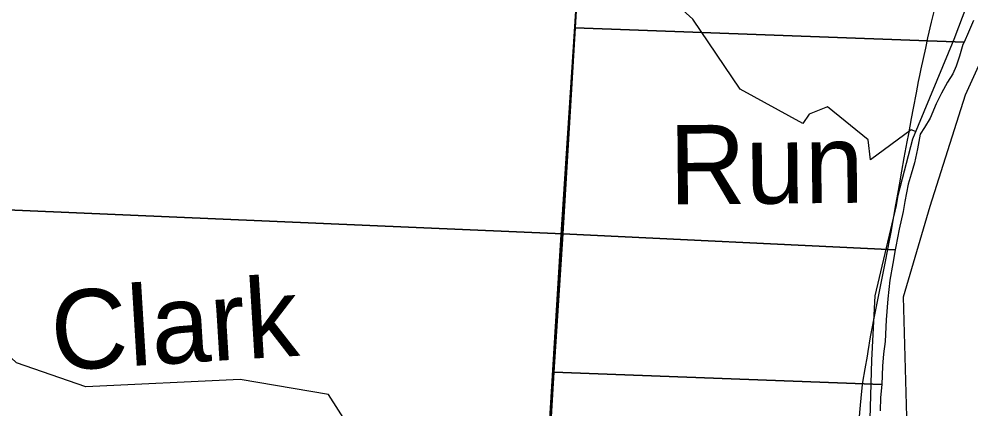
# Model space of a CAD drawing. Extents: x 21.4 to 65.3, y 4 to 26.
# Drawn here: x 25.81 to 26.947, y 22.248 to 22.714 of the extents above; entities that cross this region are included whole.
import ezdxf

# ---------------------------------------------------------------- set-up
doc = ezdxf.new("R2010")
doc.units = 0
for name, color, linetype in [('Default', 7, 'Continuous'), ('GM_X_Major_River', 7, 'Continuous'), ('GM_X_Minor_River', 7, 'Continuous'), ('GM_X_Minor_River_Text', 7, 'Continuous'), ('GM_X_Section', 7, 'Continuous'), ('GM_X_State_Route', 7, 'Continuous'), ('SH_Cut_Line', 7, 'Continuous')]:
    doc.layers.add(name, color=color, linetype=linetype)

msp = doc.modelspace()

# ---------------------------------------------------------------- linework, layer by layer
at = {"layer": 'Default'}
for points in [[(26.3906, 21.3613), (26.4573, 22.45), (26.4915, 22.9722), (26.4968, 23.0532), (26.5076, 23.2181), (26.5201, 23.4302), (26.5253, 23.5099), (26.571, 24.2838), (26.5714, 24.2916), (26.5716, 24.3007), (26.5721, 24.3116), (26.5728, 24.3278), (26.5729, 24.3421), (26.5729, 24.3464), (26.5731, 24.3575), (26.5731, 24.358), (26.5731, 24.3616), (26.5731, 24.3659), (26.5732, 24.3694), (26.5734, 24.3737), (26.5741, 24.3781), (26.6018, 24.8542), (23.5473, 24.8542), (23.5473, 20.5568)], [(29.9103, 24.8542), (26.6018, 24.8542), (26.5741, 24.3781), (26.5734, 24.3737), (26.5732, 24.3694), (26.5731, 24.3659), (26.5731, 24.3616), (26.5731, 24.358), (26.5731, 24.3575), (26.5729, 24.3464), (26.5729, 24.3421), (26.5728, 24.3278), (26.5721, 24.3116), (26.5716, 24.3007), (26.5714, 24.2916), (26.571, 24.2838), (26.5253, 23.5099), (26.5201, 23.4302), (26.5076, 23.2181), (26.4968, 23.0532), (26.4915, 22.9722), (26.4573, 22.45), (26.3906, 21.3613)], [(26.8806, 21.8662), (26.8662, 22.382), (26.8983, 22.4902), (26.9403, 22.6234), (27.1232, 23.0257), (27.1807, 23.1342), (27.2457, 23.2074), (27.2797, 23.2602), (27.35, 23.3198), (27.3927, 23.3695), (27.5383, 23.4966), (27.7231, 23.6491), (27.7926, 23.7076), (27.9329, 23.8039), (28.1831, 23.9937), (28.2398, 24.0415), (28.3384, 24.1861), (28.4624, 24.3121), (28.5577, 24.377), (28.648, 24.4047), (28.7897, 24.4217), (28.9262, 24.4567), (29.0418, 24.4692)]]:
    msp.add_lwpolyline(points, dxfattribs=at)
at = {"layer": 'GM_X_Major_River'}
msp.add_lwpolyline([(27.3721, 23.3957), (27.3499, 23.3785), (27.3039, 23.3339), (27.2682, 23.2939), (27.2227, 23.2357), (27.187, 23.179), (27.1419, 23.1192), (27.1141, 23.0781), (27.1024, 23.0556), (27.062, 22.9659), (27.006, 22.873), (26.973, 22.8129), (26.9266, 22.6893), (26.8772, 22.5703), (26.8597, 22.503), (26.8575, 22.4909), (26.8322, 22.3833), (26.828, 22.3063), (26.8227, 22.1096)], dxfattribs=at)
at = {"layer": 'GM_X_Minor_River'}
for points in [[(26.8808, 22.5795), (26.8755, 22.5813), (26.827, 22.5456), (26.8241, 22.5695), (26.7757, 22.6089), (26.7538, 22.6), (26.746, 22.5889), (26.6714, 22.63), (26.6149, 22.7137), (26.5911, 22.7352), (26.5535, 22.8498), (26.506, 22.8817), (26.4322, 22.8677), (26.3184, 22.8872), (26.2554, 22.9406), (26.295, 23.0495), (26.3006, 23.0605), (26.3209, 23.1324), (26.4231, 23.1804), (26.4997, 23.2168)], [(26.2211, 22.2005), (26.18, 22.2654), (26.0743, 22.2834), (25.8903, 22.2746), (25.8075, 22.3031), (25.723, 22.382), (25.6714, 22.4928), (25.5885, 22.5353), (25.5766, 22.5382), (25.4022, 22.4961), (25.3063, 22.4557), (25.2332, 22.3826), (25.1828, 22.2945), (25.1347, 22.283), (25.0875, 22.2959), (25.0308, 22.3887)]]:
    msp.add_lwpolyline(points, dxfattribs=at)
at = {"layer": 'GM_X_Section'}
for points in [[(25.4788, 23.5287), (26.5198, 23.4854), (26.5078, 23.2694), (26.4931, 23.0203), (26.4742, 22.7032), (26.4597, 22.4573), (25.4085, 22.5025), (25.4647, 23.2936)], [(26.9387, 22.6861), (26.9374, 22.6832), (26.9333, 22.6696), (26.9292, 22.6574), (26.9251, 22.6483), (26.919, 22.6385), (26.9119, 22.6252), (26.9055, 22.6126), (26.8983, 22.5952), (26.8916, 22.5842), (26.8863, 22.5762), (26.8829, 22.5588), (26.8796, 22.5421), (26.8755, 22.5284), (26.8721, 22.5167), (26.868, 22.4958), (26.8658, 22.4841), (26.8613, 22.4628), (26.8572, 22.442), (26.8565, 22.4383), (26.4597, 22.4573), (26.4742, 22.7032)], [(25.4085, 22.5025), (26.4597, 22.4573), (26.4491, 22.292), (26.4111, 21.6607), (26.3977, 21.4352), (25.3384, 21.4821)], [(26.8565, 22.4383), (26.8535, 22.4219), (26.8501, 22.4018), (26.8476, 22.3794), (26.8458, 22.3544), (26.8443, 22.3286), (26.8425, 22.3139), (26.8414, 22.2991), (26.8404, 22.2774), (26.4491, 22.292), (26.4597, 22.4573)]]:
    msp.add_lwpolyline(points, close=True, dxfattribs=at)
for points in [[(26.9498, 22.7121), (26.9438, 22.698), (26.9387, 22.6861), (26.4742, 22.7032), (26.4931, 23.0203), (27.0913, 22.9992)], [(26.4111, 21.6607), (26.4491, 22.292), (26.8404, 22.2774), (26.8389, 22.2616), (26.8386, 22.2457)]]:
    msp.add_lwpolyline(points, dxfattribs=at)
at = {"layer": 'GM_X_State_Route'}
msp.add_lwpolyline([(26.8136, 22.2347), (26.815, 22.2526), (26.8166, 22.2694), (26.8175, 22.2768), (26.8179, 22.2799), (26.8205, 22.2958), (26.8232, 22.3111), (26.8241, 22.3166), (26.8271, 22.3344), (26.8328, 22.3644), (26.8387, 22.3923), (26.8455, 22.4283), (26.8482, 22.4411), (26.8494, 22.4472), (26.8521, 22.4612), (26.8566, 22.4875), (26.8596, 22.5046), (26.8614, 22.5157), (26.8644, 22.5322), (26.8673, 22.5481), (26.8708, 22.567), (26.8726, 22.5768), (26.876, 22.5951), (26.8783, 22.6073), (26.8818, 22.6256), (26.8844, 22.639), (26.886, 22.6463), (26.8876, 22.6541), (26.8929, 22.679), (26.8955, 22.6912), (26.8999, 22.7099), (26.9096, 22.7504)], dxfattribs=at)
at = {"layer": 'SH_Cut_Line'}
msp.add_lwpolyline([(26.8806, 21.8662), (26.8662, 22.382), (26.8983, 22.4902), (26.9403, 22.6234), (27.1232, 23.0257), (27.1807, 23.1342), (27.2457, 23.2074), (27.2797, 23.2602), (27.35, 23.3198), (27.3927, 23.3695), (27.5383, 23.4966), (27.7231, 23.6491), (27.7926, 23.7076), (27.9329, 23.8039), (28.1831, 23.9937), (28.2398, 24.0415), (28.3384, 24.1861), (28.4624, 24.3121), (28.5577, 24.377), (28.648, 24.4047), (28.7897, 24.4217), (28.9262, 24.4567), (29.0418, 24.4692)], dxfattribs=at)

# ---------------------------------------------------------------- texts
at = {"layer": 'GM_X_Minor_River_Text'}
for s, rotation, p in [('Run', 0.5113, (26.5869, 22.4923)), ('Clark', 3.5111, (25.8513, 22.2936))]:
    msp.add_text(s, height=0.0947, rotation=rotation, dxfattribs=at).set_placement(p)

doc.saveas('drawing.dxf')
